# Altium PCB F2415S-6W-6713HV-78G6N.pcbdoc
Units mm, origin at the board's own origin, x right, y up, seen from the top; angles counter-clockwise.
Board outline 64.6 x 44.6 mm, 2 copper layers (Top Layer, Bottom Layer); 21 components, 11 nets, 44 pads, 54 vias.
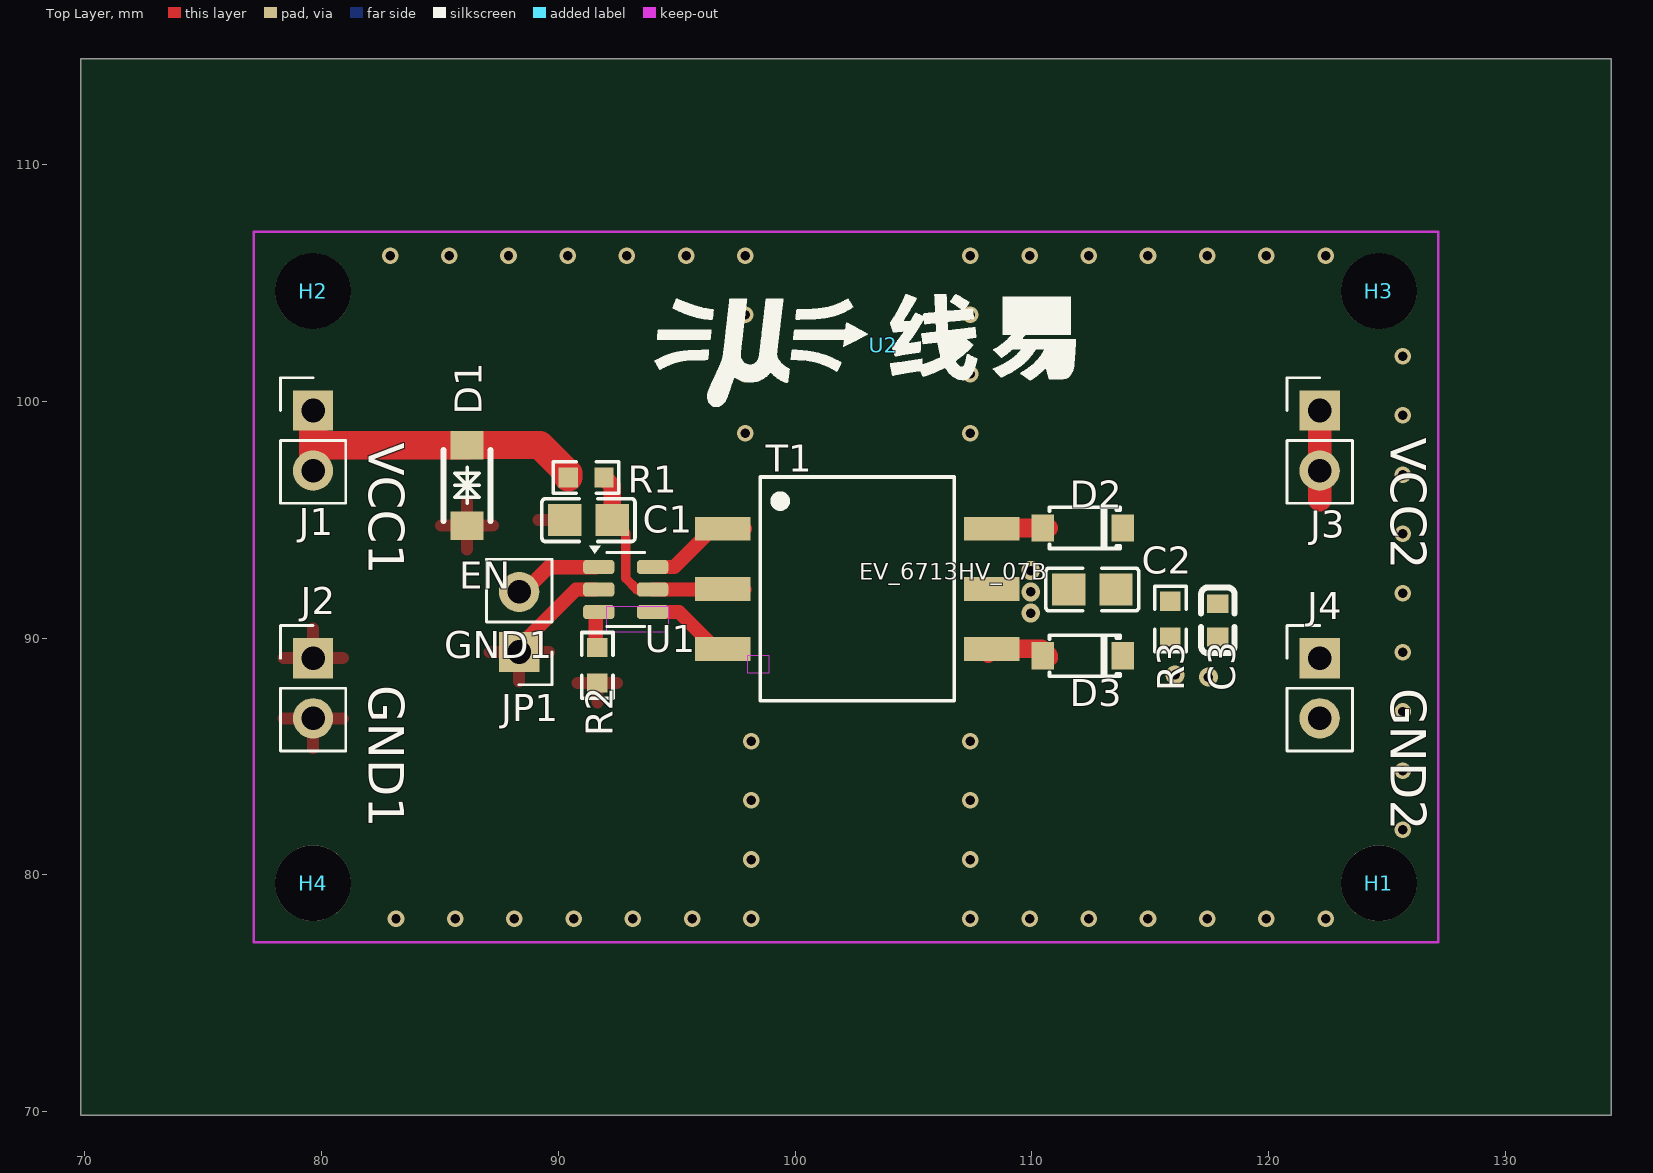
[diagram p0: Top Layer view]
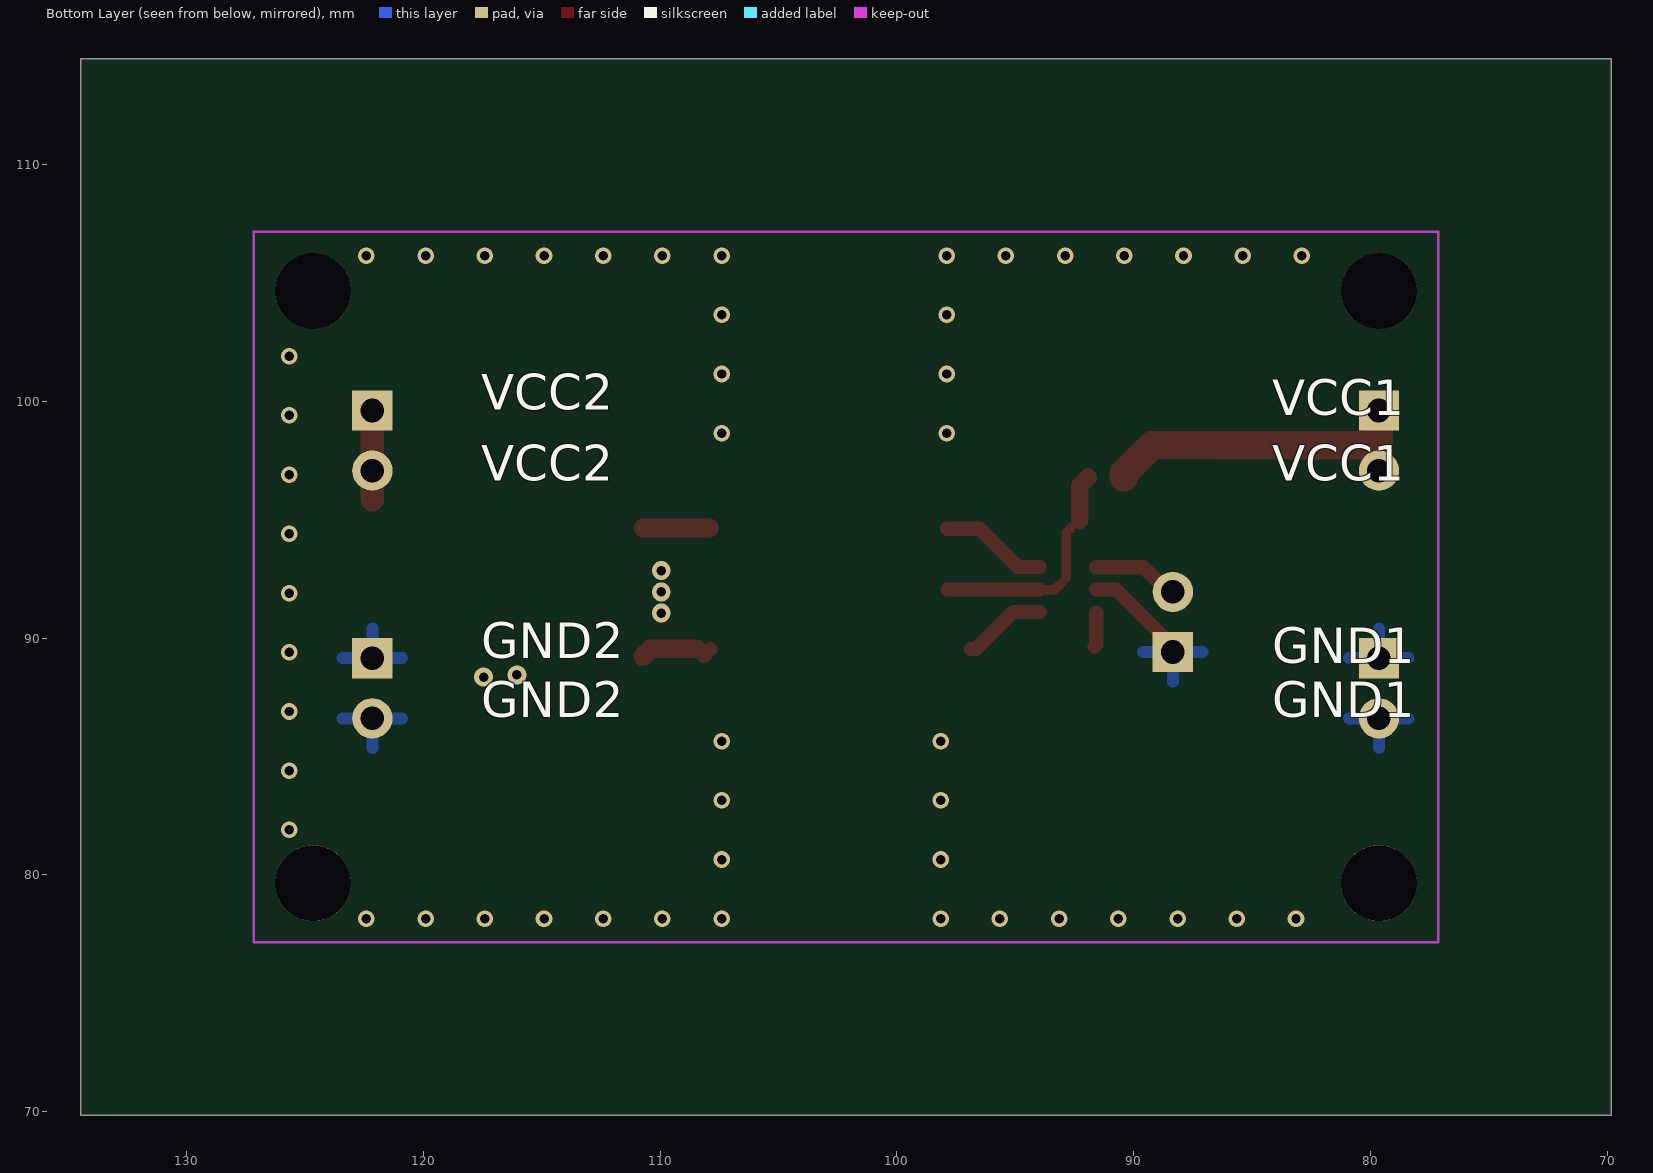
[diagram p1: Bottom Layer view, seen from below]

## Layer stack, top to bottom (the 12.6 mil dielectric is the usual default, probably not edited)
Top Layer: signal copper (thickness not stored)
Dielectric: dielectric 0.32, FR-4, Dk 4.8
Bottom Layer: signal copper (thickness not stored)

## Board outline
134.45,69.85 69.85,69.85 69.85,114.45 134.45,114.45

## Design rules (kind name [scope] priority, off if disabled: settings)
BoardOutlineClearance safeClearance [All] p0: genericclearance=0.254 ignorepadtopadclearanceinfootprint=FALSE except(0: Arc-SplitContinuation Track-SplitContinuation SMDPad-SplitContinuation THPad-SplitContinuation Via-SplitContinuation Fill-SplitContinuation Poly-SplitContinuation Region-SplitContinuation Text-SplitContinuation; 0.249: Track-CutoutEdge SMDPad-CutoutEdge THPad-CutoutEdge Via-CutoutEdge Fill-CutoutEdge Region-CutoutEdge; 0.3: Track-OutlineEdge SMDPad-OutlineEdge THPad-OutlineEdge Via-OutlineEdge Fill-OutlineEdge Region-OutlineEdge Poly-OutlineEdge Text-OutlineEdge)
Clearance safeClearance [(InNet('GND2') OR InNet('VCC2') OR InNet('GND1') OR InNet('VCC1') OR InNet('CLK') OR InNet('EN') OR InNet('$1N11') OR InNet('$1N24') OR InNet('$1N9') OR InNet('$1N21') OR InNet('$1N1'))] p1: gap=0.178 ignorepadtopadclearanceinfootprint=FALSE except(0.249: Track-Track Track-SMDPad SMDPad-SMDPad Track-THPad SMDPad-THPad THPad-THPad Track-Via SMDPad-Via THPad-Via Via-Via Track-Fill SMDPad-Fill THPad-Fill Via-Fill Fill-Fill Track-Region SMDPad-Region THPad-Region Via-Region Fill-Region Region-Region Track-Poly SMDPad-Poly THPad-Poly Via-Poly Fill-Poly Region-Poly Poly-Poly Track-Text SMDPad-Text THPad-Text Via-Text Fill-Text Region-Text Poly-Text Text-Text Track-Hole SMDPad-Hole THPad-Hole Via-Hole Fill-Hole Region-Hole Poly-Hole Text-Hole; 0.3: Track-Sheet SMDPad-Sheet THPad-Sheet Via-Sheet Fill-Sheet Region-Sheet Poly-Sheet Text-Sheet Sheet-Hole)
DiffPairsRouting differentialPair [All] p1: maxuncoupledlength=10 minlimit=5.9843 maxlimit=5.9843 mostfreqgap=5.9843 toplayer_minwidth=5 toplayer_prefwidth=10 toplayer_maxwidth=100 bottomlayer_minwidth=5 bottomlayer_prefwidth=10 bottomlayer_maxwidth=100
PasteMaskExpansion Common [All] p1: expansion=0
PlaneConnect innerPlane [All] p1: planeconnectstyle=Relief reliefexpansion=0.508 reliefentries=4 reliefconductorwidth=0.254 reliefairgap=0.254
PolygonConnect CopperRegion [All] p1: connectstyle=Relief reliefentries=4 reliefconductorwidth=20 polygonreliefangle="90 Angle" airgapwidth=15.748
PolygonConnect CopperRegion1 [All] p1: connectstyle=Direct reliefentries=4 reliefconductorwidth=0 polygonreliefangle="90 Angle" airgapwidth=20
PolygonConnect CopperRegion2 [All] p1: connectstyle=Relief reliefentries=4 reliefconductorwidth=0 polygonreliefangle="90 Angle" airgapwidth=20
PolygonConnect CopperRegion3 [All] p1: connectstyle=Relief reliefentries=4 reliefconductorwidth=0 polygonreliefangle="90 Angle" airgapwidth=20
PolygonConnect CopperRegion4 [All] p1: connectstyle=Relief reliefentries=4 reliefconductorwidth=0 polygonreliefangle="90 Angle" airgapwidth=20
RoutingVias viaSize [All] p1: viastyle="Through Hole" holewidth=12.0078 minholewidth=11.811 maxholewidth=236.1812 width=24.0158 minwidth=19.685 maxwidth=393.7008
SolderMaskExpansion Common [All] p1: useseparateexpansions=TRUE expansion=0 expansionbottom=0
Width trackWidth [All] p1: maxlimit=100 minlimit=5 preferedwidth=10

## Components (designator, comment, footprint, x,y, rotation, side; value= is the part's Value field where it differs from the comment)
C1 "CGA0805X5R106K350MT" C0805 91.276,94.98 r0 top
C2 "CC0805KKX5R8BB106_C89831" C0805 112.55,92.05 r0 top
C3 "CC0603KRX7R9BB104" C0603 117.85,90.75 r90 top
D1 "SMF28CA_C364280" SOD-123FL_L2.8-W1.8-LS3.7-BI 86.15,96.45 r270 top
D2 "DSK26_C50553" SOD-123_L2.8-W1.8-LS3.7-RD 112.15,94.65 r180 top
D3 "DSK26_C50553" SOD-123_L2.8-W1.8-LS3.7-RD 112.15,89.25 r180 top
H1 "Mechanical_MountingHole" MountingHole:MountingHole_3.2mm_M3 124.65,79.65 r0 top
H2 "Mechanical_MountingHole" MountingHole:MountingHole_3.2mm_M3 79.65,104.65 r0 top
H3 "Mechanical_MountingHole" MountingHole:MountingHole_3.2mm_M3 124.65,104.65 r0 top
H4 "Mechanical_MountingHole" MountingHole:MountingHole_3.2mm_M3 79.65,79.65 r0 top
J1 "Connector_Generic_Conn_01x02" Connector_PinHeader_2.54mm:PinHeader_1x02_P2.54mm_Vertical 79.65,99.61 r0 top
J2 "Connector_Generic_Conn_01x02" Connector_PinHeader_2.54mm:PinHeader_1x02_P2.54mm_Vertical 79.65,89.15 r0 top
J3 "Connector_Generic_Conn_01x02" Connector_PinHeader_2.54mm:PinHeader_1x02_P2.54mm_Vertical 122.15,99.61 r0 top
J4 "Connector_Generic_Conn_01x02" Connector_PinHeader_2.54mm:PinHeader_1x02_P2.54mm_Vertical 122.15,89.15 r0 top
JP1 "Jumper_Jumper_2_Open" Connector_PinHeader_2.54mm:PinHeader_1x02_P2.54mm_Vertical 88.35,89.41 r180 top
R1 "RC0603FR-071RL" R0603 91.176,96.78 r0 top
R2 "RC0603FR-0715KL" R0603 91.65,88.85 r90 top
R3 "RC0603FR-0710KL" R0603 115.85,90.8 r270 top
T1 "CMT78G6N" XFMR-SMD_6P-L9.3-W8.8-P2.54-LS12.6 102.625,92.075 r270 top
U1 "CMP6713HV" Package_TO_SOT_SMD:TSOT-23-6 92.85,92.05 r0 top
U2 "LOGO_19x5mm" MYLibrary:LOGO_19x5mm 103.722,102.362 r0 top

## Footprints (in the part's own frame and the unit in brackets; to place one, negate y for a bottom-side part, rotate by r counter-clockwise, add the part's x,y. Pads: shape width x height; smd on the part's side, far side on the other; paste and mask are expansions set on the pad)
C0603 [mm]
  rect 0.8x0.9 smd: 1(-0.7,0) 2(0.7,0)
  silkscreen extent -1.39,-0.71 1.39,0.71
C0805 [mm]
  rect 1.41x1.35 smd: 1(-1,0) 2(1,0)
  silkscreen extent -1.96,-0.9 1.96,0.9
Connector_PinHeader_2.54mm:PinHeader_1x02_P2.54mm_Vertical [mm]
  rect 1.7x1.7 hole 1: 1(0,0)
  round 1.7 hole 1: 2(0,-2.54)
  silkscreen extent -1.38,-3.92 1.38,1.38
MountingHole:MountingHole_3.2mm_M3 [mm]
  round 3.2 hole 3.2 unplated: ""(0,0)
MYLibrary:LOGO_19x5mm [mm]
  silkscreen extent -9.65,-2.6 8.13,2.16
Package_TO_SOT_SMD:TSOT-23-6 [mm]
  rrect50% 1.325x0.6 smd: 1(-1.138,0.95) 2(-1.138,0) 3(-1.138,-0.95) 4(1.137,-0.95) 5(1.137,0) 6(1.137,0.95)
  silkscreen extent -1.54,-1.56 0.8,1.84
R0603 [mm]
  rect 0.806x0.864 smd: 1(-0.753,0) 2(0.753,0)
  silkscreen extent -1.39,-0.66 1.39,0.66
SOD-123_L2.8-W1.8-LS3.7-RD [mm]
  rect 0.95x1.15 smd: 1(-1.692,0) 2(1.692,0)
  silkscreen extent -1.58,-0.87 1.41,0.87
SOD-123FL_L2.8-W1.8-LS3.7-BI [mm]
  rect 1.2x1.4 smd: 1(-1.7,0) 2(1.7,0)
  silkscreen extent -1.5,-1 1.5,1
XFMR-SMD_6P-L9.3-W8.8-P2.54-LS12.6 [mm]
  rect 1x2.34 smd: 1(-2.54,-5.67) 2(0,-5.67) 3(2.54,-5.67) 4(2.54,5.67) 5(0,5.67) 6(-2.54,5.67)
  silkscreen extent -4.73,-4.1 4.73,4.1

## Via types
v1: diameter 0.7, hole 0.4, Top Layer to Bottom Layer, 49 vias
v2: diameter 0.8, hole 0.4, Top Layer to Bottom Layer, 5 vias

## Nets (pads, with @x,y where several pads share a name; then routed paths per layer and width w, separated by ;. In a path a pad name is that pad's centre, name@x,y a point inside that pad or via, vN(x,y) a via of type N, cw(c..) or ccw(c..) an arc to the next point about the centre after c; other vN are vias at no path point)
$1N1: T1.3 U1.4 | length 3.5
  Top Layer w0.6: U1.4 95.1,91.1 96.665,89.535 T1.3@96.875,89.535
$1N9: D3.2 T1.4 | length 2.9
  Top Layer w0.6: T1.4@107.875,89.535 T1.4@108.16,89.25 ; D3.2@110.7,89.25 D3.2@110.8,89.15
  Top Layer w0.8: T1.4@108.46,89.55 110.4,89.55 D3.2@110.7,89.25
$1N11: C1.2 R1.2 T1.2 U1.5 | length 9.3
  Top Layer w0.4: C1.2@92.65,94.65 92.85,94.45 92.85,92.525 93.325,92.05 U1.5
  Top Layer w0.6: U1.5 T1.2@97.85,92.05
  Top Layer w0.749: R1.2 92.276,96.433 C1.2
$1N21: T1.1 U1.6 | length 4.6
  Top Layer w0.6: U1.6 94.9,93 96.515,94.615 T1.1@97.875,94.615
$1N24: D2.2 T1.6 | length 2.8
  Top Layer w0.6: T1.6@107.875,94.615 T1.6@107.91,94.65
  Top Layer w0.8: T1.6@107.91,94.65 D2.2@110.7,94.65
CLK: R2.2 U1.3 | length 1.5
  Top Layer w0.6: U1.3@91.58,91.085 91.58,89.72 R2.2@91.65,89.65
EN: JP1.2 U1.1 | length 3.5
  Top Layer w0.6: JP1.2@88.55,91.95 89.59,92.99 U1.1@91.58,92.99
GND1: C1.1 D1.2 J2.1 J2.2 JP1.1 R2.1 U1.2 | length 4.5
  Top Layer w0.6: JP1.1 88.35,89.65 90.75,92.05 U1.2@91.58,92.05
  other v1: 83.15,78.15 85.65,78.15 88.15,78.15 90.65,78.15 93.15,78.15 95.65,78.15 98.15,78.15 98.15,80.65 98.15,83.15 98.15,85.65 97.9,98.65 97.9,101.15 97.9,103.65 82.9,106.15 85.4,106.15 87.9,106.15 90.4,106.15 92.9,106.15 95.4,106.15 97.9,106.15
GND2: C2.1 C3.1 J4.1 J4.2 R3.2 T1.5
  other v1: 107.4,78.15 109.9,78.15 112.4,78.15 114.9,78.15 117.4,78.15 119.9,78.15 122.4,78.15 107.4,80.65 125.65,81.9 107.4,83.15 125.65,84.4 107.4,85.65 125.65,86.9 125.65,89.4 125.65,91.9 125.65,94.4 125.65,96.9 107.4,98.65 125.65,99.4 107.4,101.15 125.65,101.9 107.4,103.65 107.4,106.15 109.9,106.15 112.4,106.15 114.9,106.15 117.4,106.15 119.9,106.15 122.4,106.15
  other v2: 117.45,88.35 116.05,88.45 109.95,91.05 109.95,91.95 109.95,92.85
VCC1: D1.1 J1.1 J1.2 R1.1 | length 14.1
  Top Layer w1.199: D1.1 89.224,98.15 90.423,96.951 R1.1
  Top Layer w1.2: J1.2 J1.2@79.65,97.9 ; J1.1 J1.2@79.65,97.9 ; D1.1 79.9,98.15 J1.2@79.65,97.9
VCC2: C2.2 C3.2 D2.1 D3.1 J3.1 J3.2 R3.1 | length 3.8
  Top Layer w1: 122.15,95.85 J3.2 J3.1
pads on no net: H1. H2. H3. H4.

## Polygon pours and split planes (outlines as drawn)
VCC2 on Top Layer (solid, remove dead copper, pour order 0): 112.75,95.75 114.65,95.75 114.75,95.65 114.75,93.65 119.65,93.65 120.35,94.15 120.35,101.45 123.95,101.45 123.95,93.65 121.35,91.05 114.85,91.05 114.55,90.75 114.55,88.15 112.75,88.15
GND1 on Bottom Layer (solid, remove dead copper, pour order 6): 98.65,77.15 77.15,77.15 77.15,107.15 98.65,107.15
GND1 on Top Layer (solid, remove dead copper, pour order 2): 98.65,77.15 77.15,77.15 77.15,107.15 98.65,107.15
GND2 on Bottom Layer (solid, remove dead copper, pour order 8): 127.15,77.15 106.65,77.15 106.65,107.15 127.15,107.15
GND2 on Top Layer (solid, remove dead copper, pour order 4): 127.15,77.15 106.65,77.4 106.65,107.4 127.15,107.15

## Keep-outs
Top Layer:
  region: 98.007,89.281 98.896,89.281 98.896,88.519 98.007,88.519
  region: 92.05,91.35 94.65,91.35 94.65,90.25 92.05,90.25
Board Outline Layer:
  lines w0.1: 77.15,77.15 127.15,77.15 127.15,107.15 77.15,107.15 77.15,77.15

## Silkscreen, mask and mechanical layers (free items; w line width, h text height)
Top Silkscreen Layer:
  text "VCC2" at 125.15,98.45 h1.5 r270
  text "VCC1" at 82.005,98.25 h1.5 r270
  text "EV_6713HV_07B" at 102.706,92.456 h0.7
  text "EN" at 85.815,92.075 h1.14
  text "GND1" at 85.18,89.154 h1.14
  text "GND1" at 82.005,88.011 h1.5 r270
  text "GND2" at 125.15,87.88 h1.5 r270
Bottom Silkscreen Layer:
  text "VCC2" at 117.55,99.65 h1.5
  text "VCC1" at 84.15,99.4 h1.5
  text "VCC1" at 84.15,96.65 h1.5
  text "VCC2" at 117.55,96.65 h1.5
  text "GND2" at 117.55,89.15 h1.5
  text "GND1" at 84.15,88.94 h1.5
  text "GND1" at 84.15,86.65 h1.5
  text "GND2" at 117.55,86.65 h1.5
